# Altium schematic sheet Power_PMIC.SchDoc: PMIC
size A3; Date: 01-DEC-2013; CompanyName: STMicroelectronics; Organization: Microcontrollers Division; Address1: 12, Rue Jules HOROWITZ; Address2: 38019 Grenoble; Address3: FRANCE; DocumentNumber: MB1263; Revision: C-04; SheetNumber: 5; SheetTotal: 11; Project: STM32MP157-EVAL
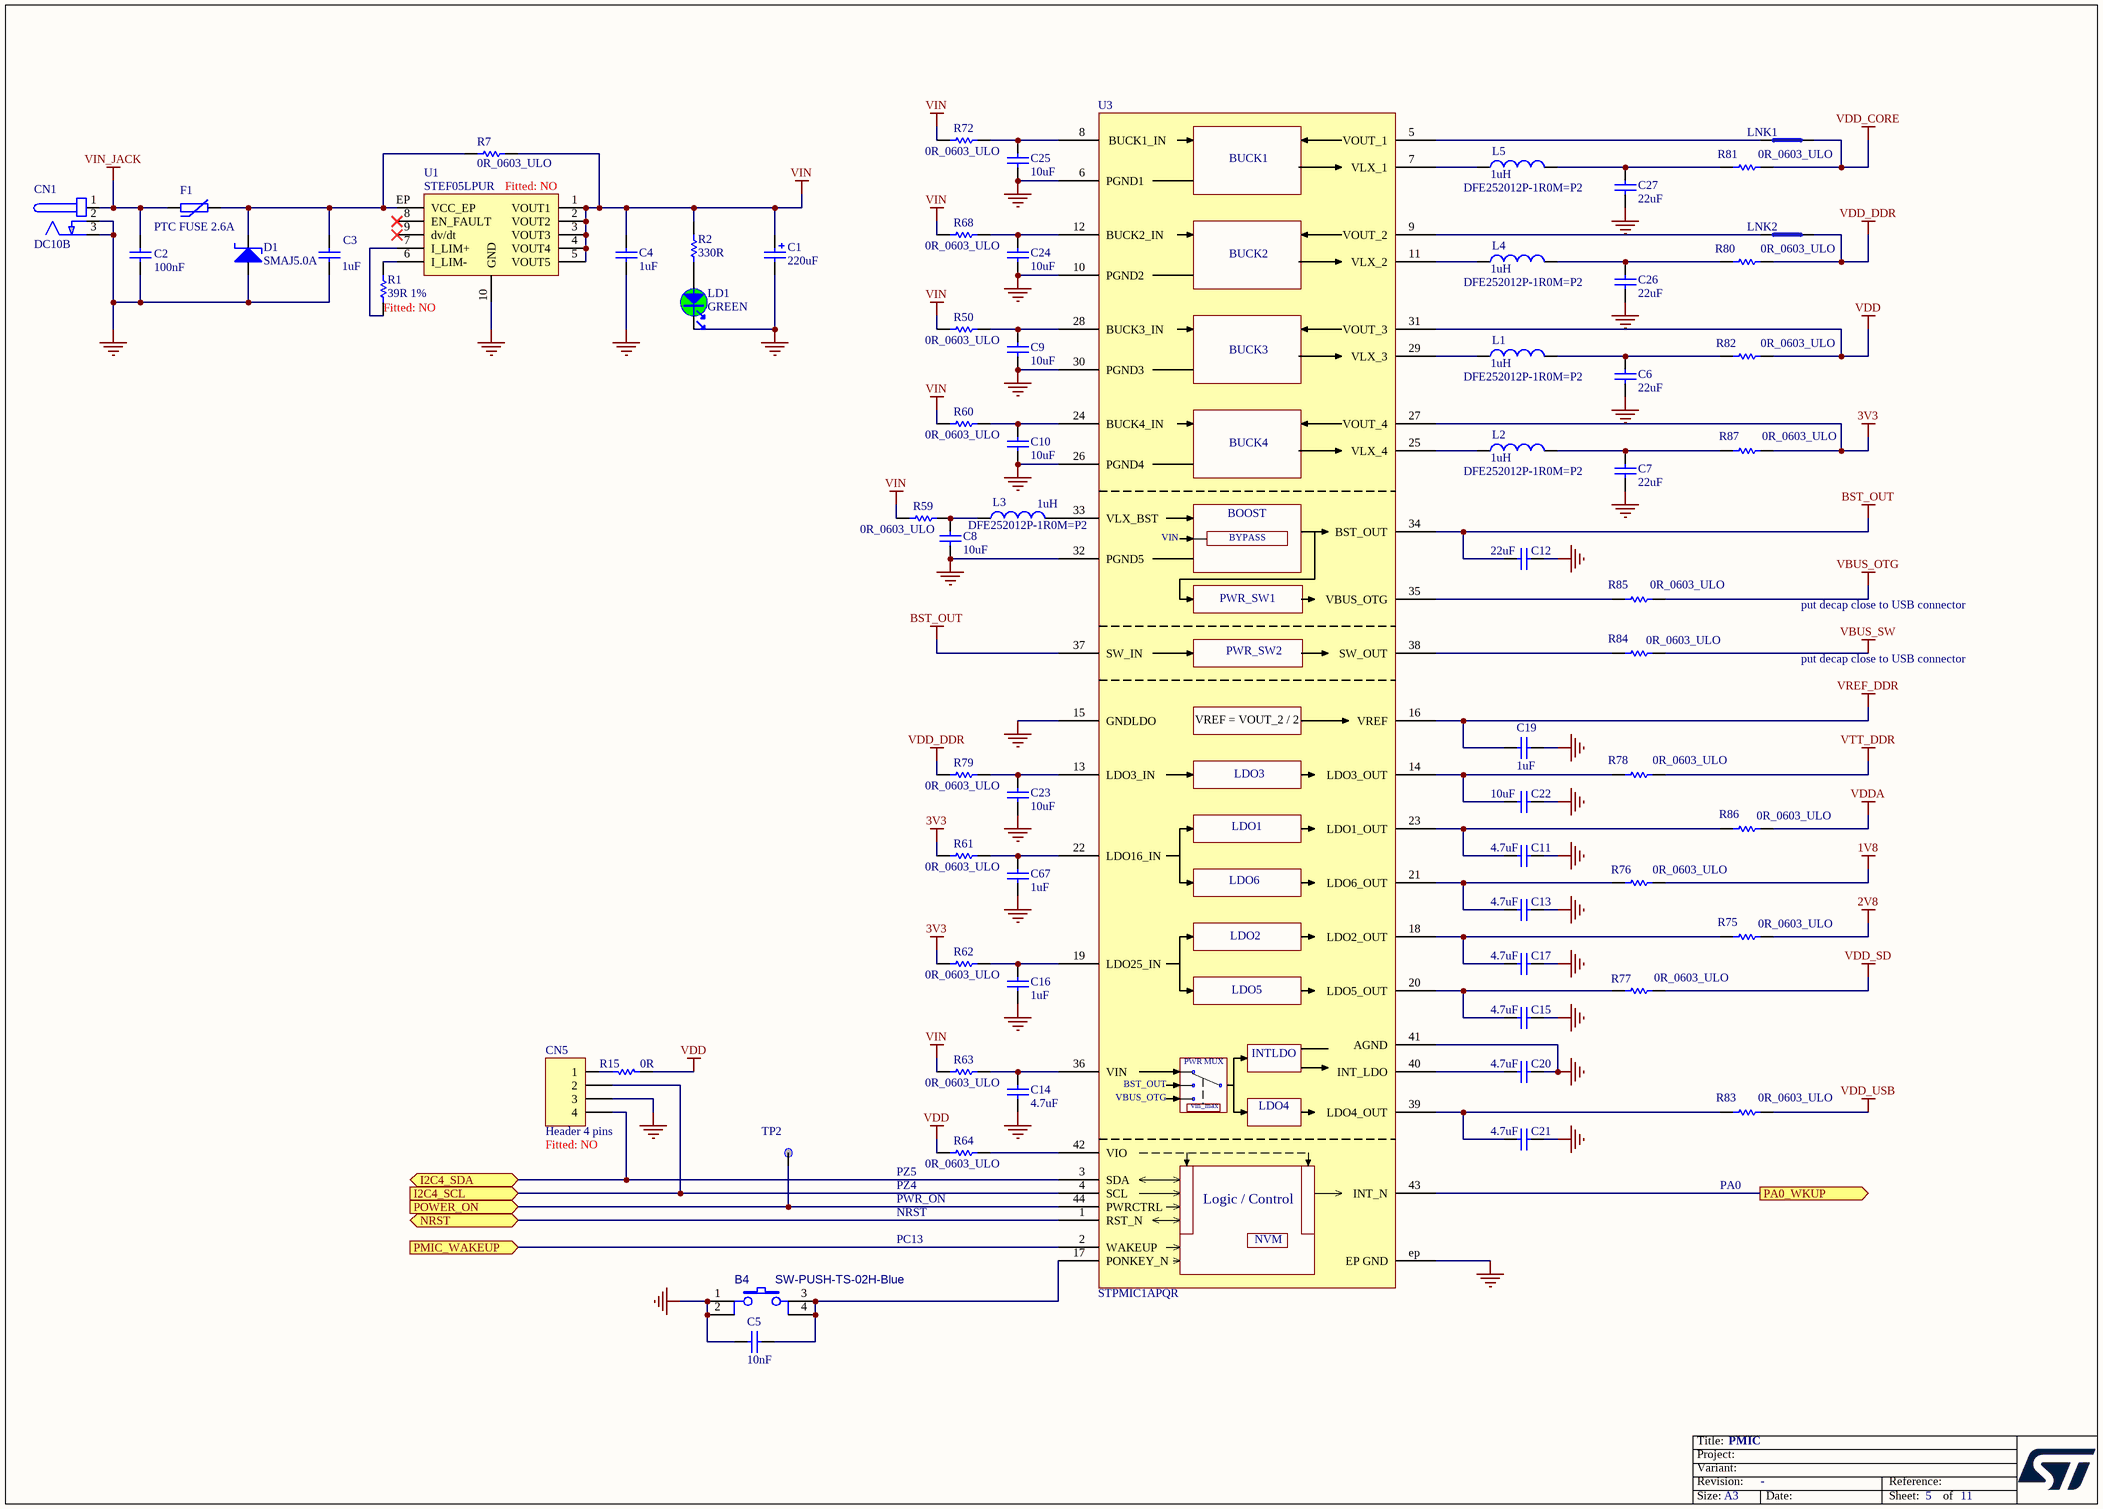
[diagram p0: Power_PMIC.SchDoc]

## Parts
B4  SW-PUSH-TS-02H-Blue  [SWI_JIUBABA_C-TS-02H-2-5-B-V-T_R_BLUE]
C1  220uF  [CPOL_TAJ-C_2312_H2P6]
C2  100nF  [C0402]
C3  1uF  [C0603]
C4  1uF  [C0603]
C5  10nF  [C0402]
C6  22uF  [C0603]
C7  22uF  [C0603]
C8  10uF  [C0603]
C9  10uF  [C0603]
C10  10uF  [C0603]
C11  4.7uF  [C0402]
C12  22uF  [C0603]
C13  4.7uF  [C0402]
C14  4.7uF  [C0402]
C15  4.7uF  [C0402]
C16  1uF  [C0402]
C17  4.7uF  [C0402]
C19  1uF  [C0402]
C20  4.7uF  [C0402]
C21  4.7uF  [C0402]
C22  10uF  [C0603]
C23  10uF  [C0603]
C24  10uF  [C0603]
C25  10uF  [C0603]
C26  22uF  [C0603]
C27  22uF  [C0603]
C67  1uF  [C0402]
CN1  DC10B  [CON_DC-POWER-SOCKET_CLIFF_FC68149_DC10B]
CN5  Header 4 pins  Fitted: NO  [CON_SAMTEC_TSW-104-07-G-S]
D1  SMAJ5.0A  [DIO_SMA_DO214-AC_1A_2K]
F1  PTC FUSE 2.6A  [PTC_BEL-FUSE_1812_0ZCG0260FF2C]
L1  Manuf_Part_1: DFE252012P-1R0M=P2  [IND_2520_TOKO_DFE252012P]  (hidden comment: 1uH)
L2  Manuf_Part_1: DFE252012P-1R0M=P2  [IND_2520_TOKO_DFE252012P]  (hidden comment: 1uH)
L3  Manuf_Part_1: DFE252012P-1R0M=P2  [IND_2520_TOKO_DFE252012P]  (hidden comment: 1uH)
L4  Manuf_Part_1: DFE252012P-1R0M=P2  [IND_2520_TOKO_DFE252012P]  (hidden comment: 1uH)
L5  Manuf_Part_1: DFE252012P-1R0M=P2  [IND_2520_TOKO_DFE252012P]  (hidden comment: 1uH)
LD1  value GREEN  [LED_0603_GREEN]  (hidden comment: LED_green)
LNK1  link_200  (value not drawn)  (no BOM)
LNK2  link_200  (value not drawn)  (no BOM)
R1  39R 1%  Fitted: NO  [R0402]
R2  330R  [R0402]
R7  0R_0603_ULO  [R0603]
R15  0R  [R0402]
R50  0R_0603_ULO  [R0603]
R59  0R_0603_ULO  [R0603]
R60  0R_0603_ULO  [R0603]
R61  0R_0603_ULO  [R0603]
R62  0R_0603_ULO  [R0603]
R63  0R_0603_ULO  [R0603]
R64  0R_0603_ULO  [R0603]
R68  0R_0603_ULO  [R0603]
R72  0R_0603_ULO  [R0603]
R75  0R_0603_ULO  [R0603]
R76  0R_0603_ULO  [R0603]
R77  0R_0603_ULO  [R0603]
R78  0R_0603_ULO  [R0603]
R79  0R_0603_ULO  [R0603]
R80  0R_0603_ULO  [R0603]
R81  0R_0603_ULO  [R0603]
R82  0R_0603_ULO  [R0603]
R83  0R_0603_ULO  [R0603]
R84  0R_0603_ULO  [R0603]
R85  0R_0603_ULO  [R0603]
R86  0R_0603_ULO  [R0603]
R87  0R_0603_ULO  [R0603]
TP2  TP  [TP_SMD_1MM]  (value not drawn)  (no BOM)
U1  STEF05LPUR  Fitted: NO  [ICC_DFN10-EPAD_3X3_P050]
U3  STPMIC1APQR  [ICC_WFQFN44-EPAD_5X6_P040]

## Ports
I2C4_SCL (in), I2C4_SDA (bidir), NRST (bidir), PA0_WKUP (out), PMIC_WAKEUP (in), POWER_ON (in)

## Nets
1V8: R76.2
2V8: R75.2
3V3: R61.1 R62.1 R87.2 U3.27(VOUT_4)
BST_OUT: C12.2 U3.34(BST_OUT) U3.37(SW_IN)
GND: B4.1 B4.2 C1.2 C2.1 C3.1 C4.1 C5.1 C6.1 C7.1 C8.1 C9.1 C10.1 C11.1 C12.1 C13.1 C14.1 C15.1 C16.1 C17.1 C19.1 C20.2 C21.1 C22.1 C23.1 C24.1 C25.1 C26.1 C27.1 C67.1 CN1.2 CN1.3 CN5.3 D1.1(A) LD1.2 U1.10(GND) U3.6(PGND1) U3.10(PGND2) U3.15(GNDLDO) U3.26(PGND4) U3.30(PGND3) U3.32(PGND5) U3.41(AGND) U3.ep(EP_GND)
VBUS_OTG: R85.2
VBUS_SW: R84.2
VDD: R15.2 R64.1 R82.2 U3.31(VOUT_3)
VDD_CORE: LNK1.2 R81.2
VDD_DDR: LNK2.2 R79.1 R80.2
VDD_SD: R77.2
VDD_USB: R83.2
VDDA: R86.2
VIN: C1.1 C4.2 R2.2 R7.2 R50.1 R59.1 R60.1 R63.1 R68.1 R72.1 U1.1(VOUT1) U1.2(VOUT2) U1.3(VOUT3) U1.4(VOUT4) U1.5(VOUT5)
VIN_JACK: C2.2 CN1.1 F1.1
VREF_DDR: C19.2 U3.16(VREF)
VTT_DDR: R78.2
I2C4_SCL: CN5.2 U3.4(SCL) ; port I2C4_SCL
I2C4_SDA: CN5.4 U3.3(SDA) ; port I2C4_SDA
NRST: U3.1(RST_N) ; port NRST
PA0_WKUP: U3.43(INT_N) ; port PA0_WKUP
PMIC_WAKEUP: U3.2(WAKEUP) ; port PMIC_WAKEUP
POWER_ON: TP2.1 U3.44(PWRCTRL) ; port POWER_ON
NetB4_3: B4.3 B4.4 C5.2 U3.17(PONKEY_N)
NetC3_2: C3.2 D1.2(K) F1.2 R7.1 U1.EP(VCC_EP)
NetC6_2: C6.2 L1.2 R82.1
NetC7_2: C7.2 L2.2 R87.1
NetC8_2: C8.2 L3.1 R59.2
NetC9_2: C9.2 R50.2 U3.28(BUCK3_IN)
NetC10_2: C10.2 R60.2 U3.24(BUCK4_IN)
NetC11_2: C11.2 R86.1 U3.23(LDO1_OUT)
NetC13_2: C13.2 R76.1 U3.21(LDO6_OUT)
NetC14_2: C14.2 R63.2 U3.36(VIN)
NetC15_2: C15.2 R77.1 U3.20(LDO5_OUT)
NetC16_2: C16.2 R62.2 U3.19(LDO25_IN)
NetC17_2: C17.2 R75.1 U3.18(LDO2_OUT)
NetC20_1: C20.1 U3.40(INT_LDO)
NetC21_2: C21.2 R83.1 U3.39(LDO4_OUT)
NetC22_2: C22.2 R78.1 U3.14(LDO3_OUT)
NetC23_2: C23.2 R79.2 U3.13(LDO3_IN)
NetC24_2: C24.2 R68.2 U3.12(BUCK2_IN)
NetC25_2: C25.2 R72.2 U3.8(BUCK1_IN)
NetC26_2: C26.2 L4.2 R80.1
NetC27_2: C27.2 L5.2 R81.1
NetC67_2: C67.2 R61.2 U3.22(LDO16_IN)
NetCN5_1: CN5.1 R15.1
NetL1_1: L1.1 U3.29(VLX_3)
NetL2_1: L2.1 U3.25(VLX_4)
NetL3_2: L3.2 U3.33(VLX_BST)
NetL4_1: L4.1 U3.11(VLX_2)
NetL5_1: L5.1 U3.7(VLX_1)
NetLD1_1: LD1.1 R2.1
NetLNK1_1: LNK1.1 U3.5(VOUT_1)
NetLNK2_1: LNK2.1 U3.9(VOUT_2)
NetR1_1: R1.1 U1.7(I_LIM+)
NetR1_2: R1.2 U1.6(I_LIM-)
NetR64_2: R64.2 U3.42(VIO)
NetR84_1: R84.1 U3.38(SW_OUT)
NetR85_1: R85.1 U3.35(VBUS_OTG)

Not connected (* = marked no-connect by the designer): U1 8(EN_FAULT)* 9(dv/dt)*

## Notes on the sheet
- put decap close to USB connector
- (near R64) PZ5
- (near R64) PZ4
- PA0
- NRST
- (near R64) PWR_ON
- PC13

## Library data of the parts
B4 = SW-PUSH-TS-02H-Blue: TS-02H SMD Light Touch Switch blue; Manuf_1: Jiubaba; Manuf_Part_1: C-TS-02H-2.5-K-V-T/R BLUE; Fitted: YES; Ordered_By: subcon
C1 = Cap_220uF_POL_10%_TAJA: Polarized Capacitor,220uF,10V,10%,AVX; Manuf_Part_1: TAJC227K010R; Fitted: YES; Ordered_By: Subcon
C2 = Cap_100nF_X7R_10%_0402: Capacitor,100nF,16V,X7R,10%,0402,YAGEO; Manuf_Part_1: CC0402KRX7R7BB104; Fitted: YES; Ordered_By: Subcon
C3 C4 = Cap_1uF_X5R_10%_0603: Capacitor,1uF,16V,X5R,10%,0603,YAGEO; Manuf_Part_1: CC0603KRX5R7BB105; Fitted: YES; Ordered_By: Subcon
C5 = Cap_10nF_X7R_10%_0402: Capacitor,10nF,16V,X7R,10%,0402,YAGEO; Manuf_Part_1: CC0402KRX7R7BB103; Fitted: YES; Ordered_By: Subcon
C6 C7 C12 C26 C27 = Cap_22uF_X5R_20%_0603_MURATA: Capacitor MLCC 22µF 20% 6,3V 7,5µF@3,3V ESR=4mohm@100kHz  Z=5mohm@2MHz X5R 0603; Manuf_Part_1: GRM188R60J226MEA0J; Manuf_1: MURATA; Fitted: YES; Ordered_By: Subcon
C8-C10 C22-C25 = Cap_10uF_X5R_10%_0603_MURATA: Capacitor MLCC 10µF 10% 10V 2,5µF@5,5V Z=5mohm@2MHz X5R 0603; Manuf_Part_1: GRM188R61A106KE69D; Manuf_1: MURATA; Fitted: YES; Ordered_By: Subcon
C11 C13-C15 C17 C20 C21 = Cap_4.7uF_X5R_20%_6V3_0402: Capacitor MLCC 4,7µF 20% 6,3V 1,9uF@3,3V X5R 0402; Manuf_Part_1: GRM155R60J475ME47; Manuf_1: MURATA; Fitted: YES; Ordered_By: Subcon
C16 C19 C67 = Cap_1uF_X5R_10%_6V3_0402: Capacitor MLCC 1µF 10% 6,3V 0,4uF@3,3V X5R 0402 MURATA; Manuf_Part_1: GRM155R61E105KA12; Fitted: YES; Ordered_By: Subcon
CN1 = CONN_Power_DC10B: DC Power Jack 2.5mm 5A Right Angle through hole; Manuf_Part_1: DC-10B; Manuf_1: CLIFF; Ordered_By: Subcon; Fitted: YES
CN5 = Header 4: Header, 4-Pin; Manuf_1: Samtec; Manuf_Part_1: TSW-104-07-x-S; Ordered_By: Subcon
D1 = SMAJ5.0A-TR: Transil unidirectional diode Vrm=5.0V, Vbr=6.4V(10mA), Vcl=13.4V(174A), SMA; Manuf_1: STM; Ordered_By: Subcon; ECCN_US/EU: EAR99/NEC; Fitted: YES
F1 = 0ZCG0260FF2C: SMD, PTC resettable fuse, IH:2.6A, IT:5A, Vdc_max:8V, Rmax:47mohm, BELFUSE; Fitted: YES; Ordered_By: Subcon
L1-L5 = IND_1uH_42mohm_3.2A: SMD power inductor. 1µH, 3,2A, 42mohm, 2,5x2,0x1,2mm; Manuf_1: Murata; Ordered_By: Subcon; Fitted: YES
LD1 = MCD-02900: LED, Green, 2V, 25mA, 0603, SMD; Part_Type: Display; Part_Preference: Recommended; Manufacturer: EVERLIGHT; Manufacturer_Part_Number: 19-213SYGC/S530-E2/5T; Full_Alternate_Internal_Part_Number: MCD-00320; Partial_Alternate_Internal_Part_Number: MCD-00050; Component_Country_Of_Origin: China; ShowFields: YES; ID: 5016
LNK1 LNK2 = link_200: link 0.2mm
R1 = Res_39_1%_0402: Resistor,39R,0402,1%,YAGEO; Manuf_Part_1: RC0402FR-0739RL; Ordered_By: Subcon
R2 = Res_330_1%_0402: Resistor,330R,0402,1%,YAGEO; Manuf_Part_1: RC0402FR-07330RL; Fitted: YES; Ordered_By: Subcon
R7 R50 R59-R64 R68 R72 R75-R87 = Res_0_ULO_0603: Resistor,0R,0603,ULO,ROHM; Manuf_Part_1: PMR03EZPJ000; Fitted: YES; Ordered_By: subcon
R15 = Res_0_5%_0402: Resistor,0R,0402,5%,YAGEO; Manuf_Part_1: RC0402JR-070RL; Order_Code: 2363467; Fitted: YES; Ordered_By: Subcon
TP2 = TP 1mm: Test Point; Fitted: YES
U1 = STEF05LPUR: Electronic fuse for 5V line, 3.6A max, DFN10(3x3mm); Manuf_1: STM; Ordered_By: Subcon
U3 = STPMIC1A: PMIC WFQFN 5.0x6.0x0.8 44L 0.4 pitch; Provided: ST; Ordered_By: Subcon; ECCN_US/EU: EAR99/NEC; Fitted: YES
